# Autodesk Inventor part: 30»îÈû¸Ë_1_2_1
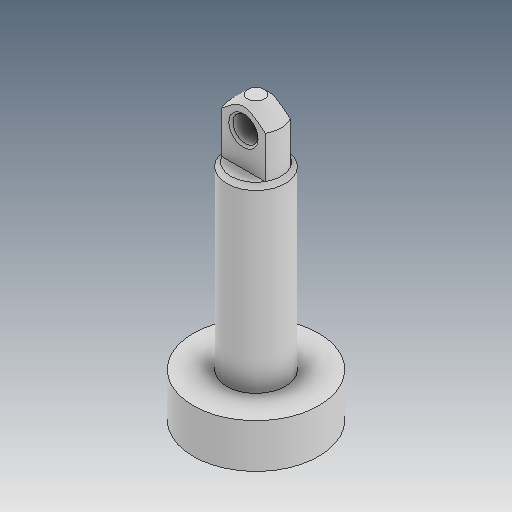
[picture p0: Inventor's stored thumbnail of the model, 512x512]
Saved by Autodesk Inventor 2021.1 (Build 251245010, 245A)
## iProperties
Created: 2019-04
Part Number: 30»îÈû¸Ë_1_2_1
Material: Ogólny
Document SubType Name: Modeling
Designer: user
Density: 1 g/cm^3
Appearance: Domyślna
Author: user
Revision Number: ÈÎºÎ
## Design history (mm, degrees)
feature "Í¹Ì¨-À­Éì1"
node "Bryła1"
